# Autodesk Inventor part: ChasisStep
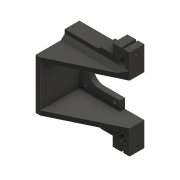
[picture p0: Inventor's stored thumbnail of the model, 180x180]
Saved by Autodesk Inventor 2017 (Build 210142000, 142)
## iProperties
Created: 2018-08
Part Number: ChasisStep
Material: Plastic, Opaque Black
Document SubType Name: Modeling
Designer: JK
Density: 0.952 g/cm^3
Appearance: Smooth - Black
Author: JK
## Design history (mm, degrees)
sketch "Sketch1"
  geometry: L1 (-21, 21)-(21, 21); L2 (21, 21)-(21, -21); L3 (21, -21)-(-21, -21); L4 (-21, -21)-(-21, 21); L5 (-21, 21)-(21, -21); L6 (21, 21)-(-21, -21); L7 (0, 11.5)-(-21, 11.5); L8 (0, -11.5)-(-21, -11.5); C1 r 1.75 at (15.5, 15.5); C2 r 1.75 at (15.5, -15.5); C3 r 1.75 at (-15.5, -15.5); C4 r 1.75 at (-15.5, 15.5); A1 r 11.5 centre (0, 0) between (0, -11.5) and (0, 11.5); 1 further point
  constraints: 16 end point, 6 point on line, 5 centre point, 3 equal radius, 3 perpendicular, 2 horizontal alignment, 2 midpoint, 2 parallel, 2 point on circle, 2 tangent, 2 vertical alignment, 1 coincident, 1 horizontal
  dimensions: "d0" = 23 diameter of A1; "d1" = 42 distance of L1.end L2.end; "d2" = 42 distance of L2.end L3.end; "d3" = 3.5 diameter of C1; "d4" = 31 distance of C1.centre C2.centre
extrude "Extrusion1" new body sketch "Sketch1" distance "d5" = 5; taper "d6" = 0 deg
sketch "Sketch3"
  geometry: L1 (0, 5)-(42, 5); L2 (42, 5)-(42, -40); L3 (42, -40)-(0, -40); L4 (0, -40)-(0, 5); L5 (0, 0)-(0, 5) reference; L6 (42, 0)-(42, 5) reference; L7 (0, 5)-(42, 5) reference; 1 further point
  constraints: 8 end point, 3 collinear, 2 parallel, 1 horizontal, 1 perpendicular
  dimensions: "d7" = 45 distance of L1.end L2.end
extrude "Extrusion2" join sketch "Sketch3" distance "d8" = 5; taper "d9" = 0 deg
sketch "Sketch4"
  geometry: L1 (0, -40)-(0, 0) reference; L2 (0, 0)-(-42, 0); L3 (-42, 0)-(-42, -40); L4 (-42, -40)-(0, -40); L5 (0, -40)-(0, 0); 1 further point
  constraints: 8 end point, 2 parallel, 1 horizontal, 1 perpendicular
extrude "Extrusion3" cut sketch "Sketch4" distance "d10" = 0.5; taper "d11" = 0 deg
workplane "Work Plane2"
sketch "Sketch5"
  geometry: L1 (-47, -40)-(-47, 5) reference; L2 (0, 5)-(-47, 5); L3 (-47, 5)-(-47, -40); L4 (0, 5)-(-47, 5) reference; L5 (-42.5, -40)-(-47, -40) reference; L6 (-47, -40)-(-42.5, -40); L7 (0, 0)-(0, 5) reference; L8 (0, 5)-(-21, 5) reference; L9 (0, 5)-(0, -10); L10 (-42.5, 0)-(-42.5, -40) reference; L11 (0, -10)-(-42.5, -40); 1 further point
  constraints: 10 end point, 2 horizontal, 1 collinear, 1 vertical
  dimensions: "d29" = 15 distance of L2.start L9.end
extrude "Extrusion4" join sketch "Sketch5" distance "d12" = 5; taper "d13" = 0 deg
mirror "Mirror1"
sketch "Sketch6"
  geometry: L1 (10, 0)-(-33, 0); L2 (-33, 0)-(-33, -43.504); L3 (-33, -43.504)-(10, -43.504); L4 (10, -43.504)-(10, 0); 2 further points
  constraints: 8 end point, 2 parallel, 1 horizontal, 1 perpendicular
  dimensions: "d14" = 0.5 distance from line of point (9.5, 0) L4; "d15" = 43 distance of L2.end L3.end
extrude "Extrusion5" cut sketch "Sketch6" stored distance "d16" = 21.25; taper "d17" = 0 deg
sketch "Sketch7"
  geometry: L1 (11, 21.5)-(41, 21.5); L2 (41, 21.5)-(41, 46.5); L3 (41, 46.5)-(11, 46.5); L4 (11, 46.5)-(11, 21.5); L5 (21, 11.5)-(21, 26) reference; 1 further point
  constraints: 8 end point, 2 parallel, 1 horizontal, 1 perpendicular
  dimensions: "d19" = 25 distance of L1.end L2.end; "d20" = 30 distance between parallel lines of L4 L2; "d21" = 20 distance between parallel lines of L5 L2
extrude "Extrusion6" join sketch "Sketch7" distance "d22" = 15; taper "d23" = 0 deg
sketch "Sketch8"
  geometry: L1 (41, 21.5)-(41, 46.5) reference; L2 (41, 46.5)-(11, 46.5) reference; L3 (21, 21.5)-(41, 21.5) reference; C1 r 4.15 at (33.5, 34); 1 further point
  constraints: 1 centre point
  dimensions: "d24" = 8.3 diameter of C1; "d25" = 7.5 distance from line of L1 C1.centre; "d55" = 12.5 distance from line of L3 C1.centre
extrude "Extrusion7" cut sketch "Sketch8" distance "d27" = 22.5; taper "d28" = 0 deg
chamfer "Chamfer1" distance "d30" = 10.5; stored, may be unused: second distance "d31" = 2, angle "d32" = 45 deg
sketch "Sketch9"
  geometry: L1 (20, -10)-(0, -10) reference; L2 (0, -10)-(-42.5, -40) reference; L3 (20, -10)-(-42.5, -40); L4 (-42.5, -40)-(0, -10) reference; L5 (-42.5, -40)-(0, -10); L6 (-10, -10)-(20, -10) reference; L7 (0, -10)-(20, -10); 2 further points
  constraints: 6 end point, 2 collinear
extrude "Extrusion8" join sketch "Sketch9" stored distance "d33" = 10; taper "d34" = 0 deg
mirror "Mirror2"
chamfer "Chamfer3" distance "d48" = 10.5; stored, may be unused: second distance "d49" = 2, angle "d50" = 45 deg
sketch "Sketch12"
  geometry: L1 (30, 0)-(0, 0) reference; L2 (0, 0)-(0, -10) reference; L3 (12.686, 0)-(0, 0); L4 (0, 0)-(0, -10); L5 (0, -10)-(12.686, -10); L6 (12.686, -10)-(12.686, 0); L7 (0, -83)-(0, -93) reference; L8 (0, -93)-(30, -93) reference; L9 (0, -83)-(12.686, -83); L10 (12.686, -83)-(12.686, -93); L11 (12.686, -93)-(0, -93); L12 (0, -93)-(0, -83); 1 further point
  constraints: 16 end point, 4 parallel, 3 point on line, 2 horizontal, 2 perpendicular
extrude "Extrusion11" cut sketch "Sketch12" distance "d56" = 27; taper "d57" = 0 deg
sketch "Sketch13"
  geometry: L1 (-6.5, 25.947)-(-8.5, 25.947); L2 (-8.5, 25.947)-(-8.5, 8.066); L3 (-8.5, 8.066)-(-6.5, 8.066); L4 (-6.5, 8.066)-(-6.5, 25.947); L5 (-6.5, -59.15)-(-8.5, -59.15); L6 (-8.5, -59.15)-(-8.5, -77.172); L7 (-8.5, -77.172)-(-6.5, -77.172); L8 (-6.5, -77.172)-(-6.5, -59.15); L9 (0, 20.5)-(0, 0) reference; L10 (0, -72.5)-(0, -52) reference; 1 further point
  constraints: 16 end point, 4 parallel, 2 horizontal, 2 perpendicular
  dimensions: "d58" = 2 distance of L6.end L7.end; "d59" = 2 distance of L1.start L1.end; "d60" = 6.5 distance between parallel lines of L9 L4; "d61" = 6.5 distance between parallel lines of L10 L8
extrude "Extrusion12" cut sketch "Sketch13" distance "d62" = 27; taper "d63" = 0 deg
sketch "Sketch14"
  geometry: L1 (93, 0)-(93, -15) reference; L2 (0, 0)-(0, -15) reference; C1 r 1.85 at (4.5, -7.5); C2 r 1.85 at (88.5, -7.5); 1 further point
  constraints: 2 centre point
  dimensions: "d64" = 3.7 diameter of C1; "d65" = 3.7 diameter of C2; "d66" = 4.5 distance from line of L1 C2.centre; "d67" = 4.5 distance from line of L2 C1.centre
extrude "Extrusion13" cut sketch "Sketch14" distance "d68" = 27; taper "d69" = 0 deg
sketch "Sketch15"
  geometry: L1 (-26, -26)-(-26, 26) reference; L2 (-26, 26)-(11, 26); L3 (11, 26)-(11, 34); L4 (11, 34)-(-26, 34); L5 (-26, 34)-(-26, 26); L6 (-26, 26)-(-26, -26) reference; L7 (-26, -26)-(11, -26); L8 (11, -26)-(11, -34); L9 (11, -34)-(-26, -34); L10 (-26, -34)-(-26, -26); 3 further points
  constraints: 16 end point, 4 parallel, 2 horizontal, 2 perpendicular, 2 vertical alignment, 1 collinear
  dimensions: "d74" = 68 distance between parallel lines of L9 L4
extrude "Extrusion14" join sketch "Sketch15" distance "d75" = 15; taper "d76" = 0 deg
sketch "Sketch16"
  geometry: L1 (8.5, 34)-(-26, 34) reference; L2 (-26, 34)-(-26, -34) reference; L3 (8.5, -34)-(-26, -34) reference; C1 r 4.8 at (-19.5, 27.5); C2 r 4.8 at (-19.5, -27.5); 1 further point
  constraints: 2 centre point
  dimensions: "d77" = 9.6 diameter of C1; "d78" = 9.6 diameter of C2; "d79" = 6.5 distance from line of C1.centre L1; "d80" = 6.5 distance from line of C1.centre L2; "d81" = 6.5 distance from line of L2 C2.centre; "d82" = 6.5 distance from line of L3 C2.centre
extrude "Extrusion15" cut sketch "Sketch16" distance "d83" = 10; taper "d84" = 0 deg
chamfer "Chamfer6" distance "d85" = 4; stored, may be unused: second distance "d86" = 2, angle "d87" = 45 deg
body "Solid1"
